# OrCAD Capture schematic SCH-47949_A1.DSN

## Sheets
1 01 TITLE PAGE: title: OM27160B1HN; rev: A1; company: NXP Semiconductors; note: SCH-47949 PDF: SPF-47949; note: 6501 William Cannon Drive West; note: Austin, TX 78735-8598
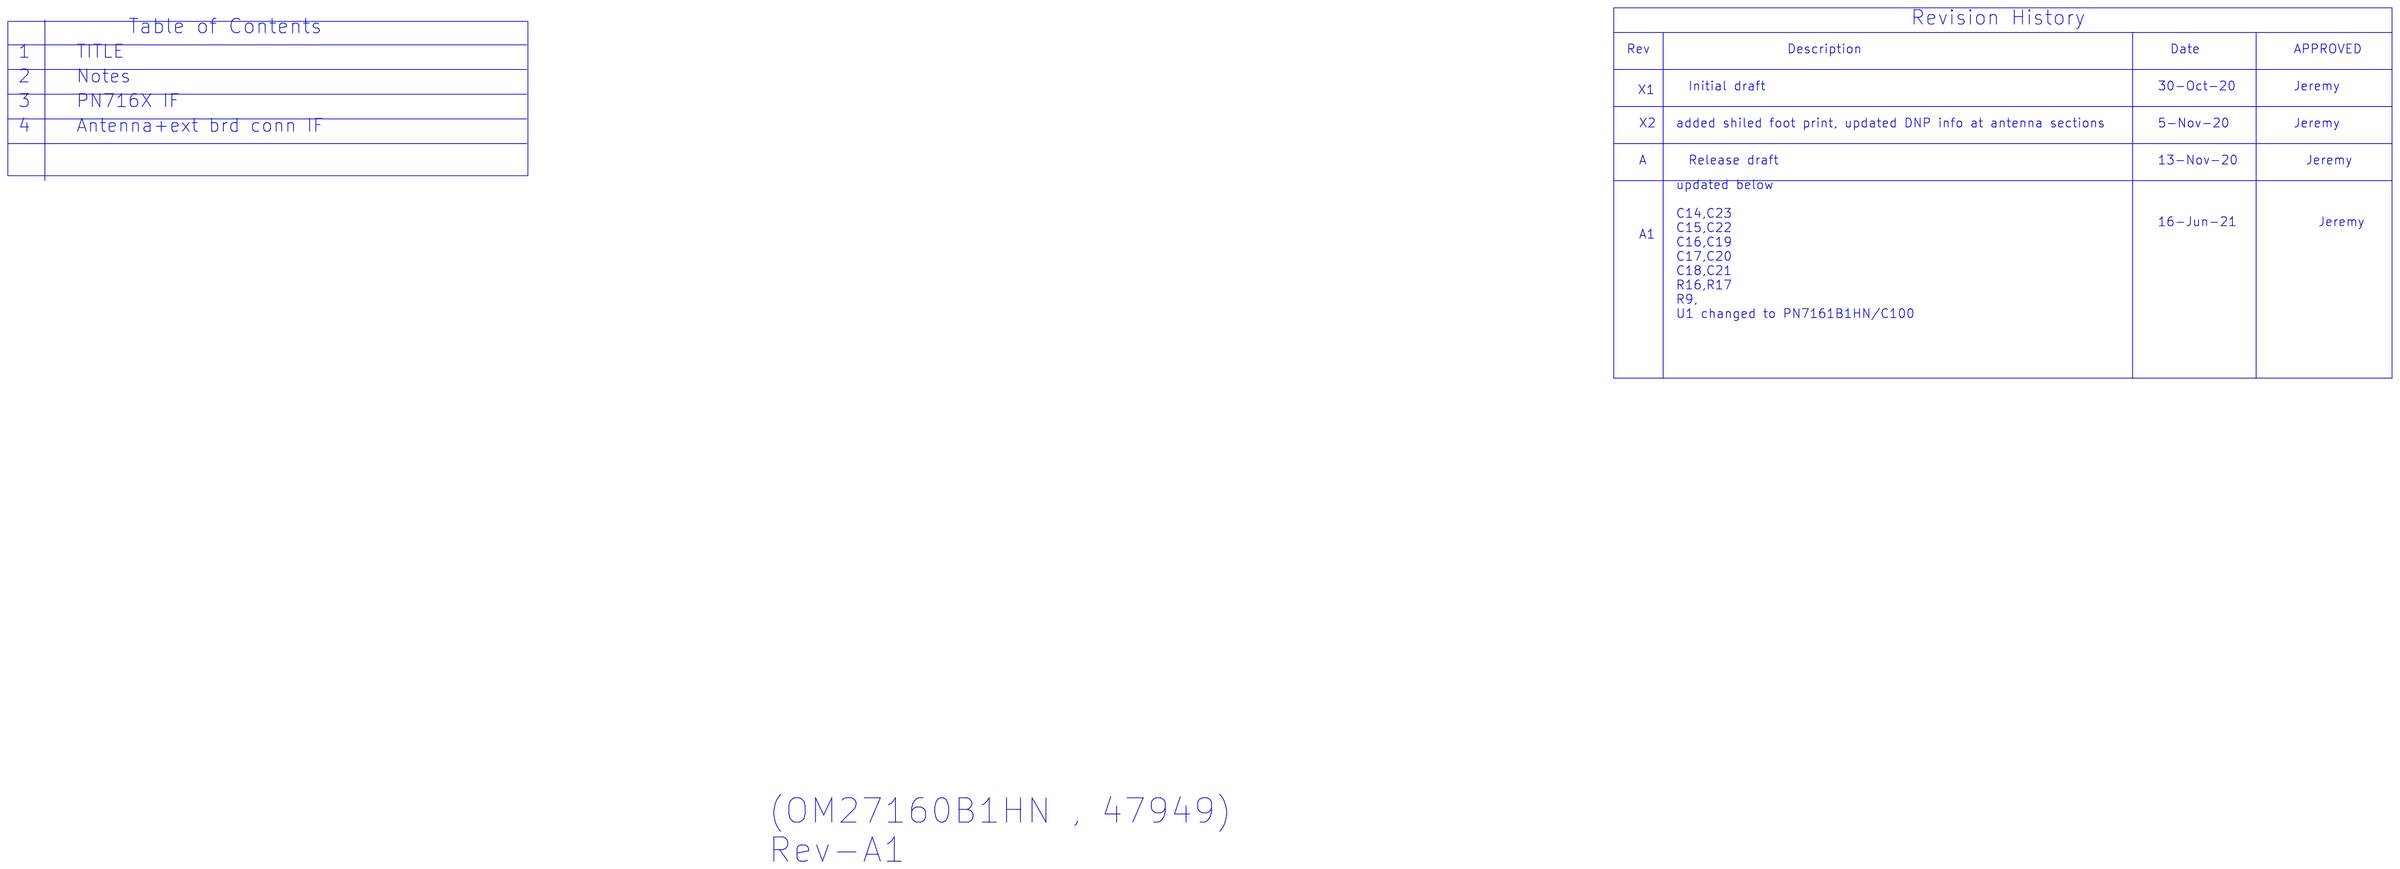
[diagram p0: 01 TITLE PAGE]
2 02 Notes
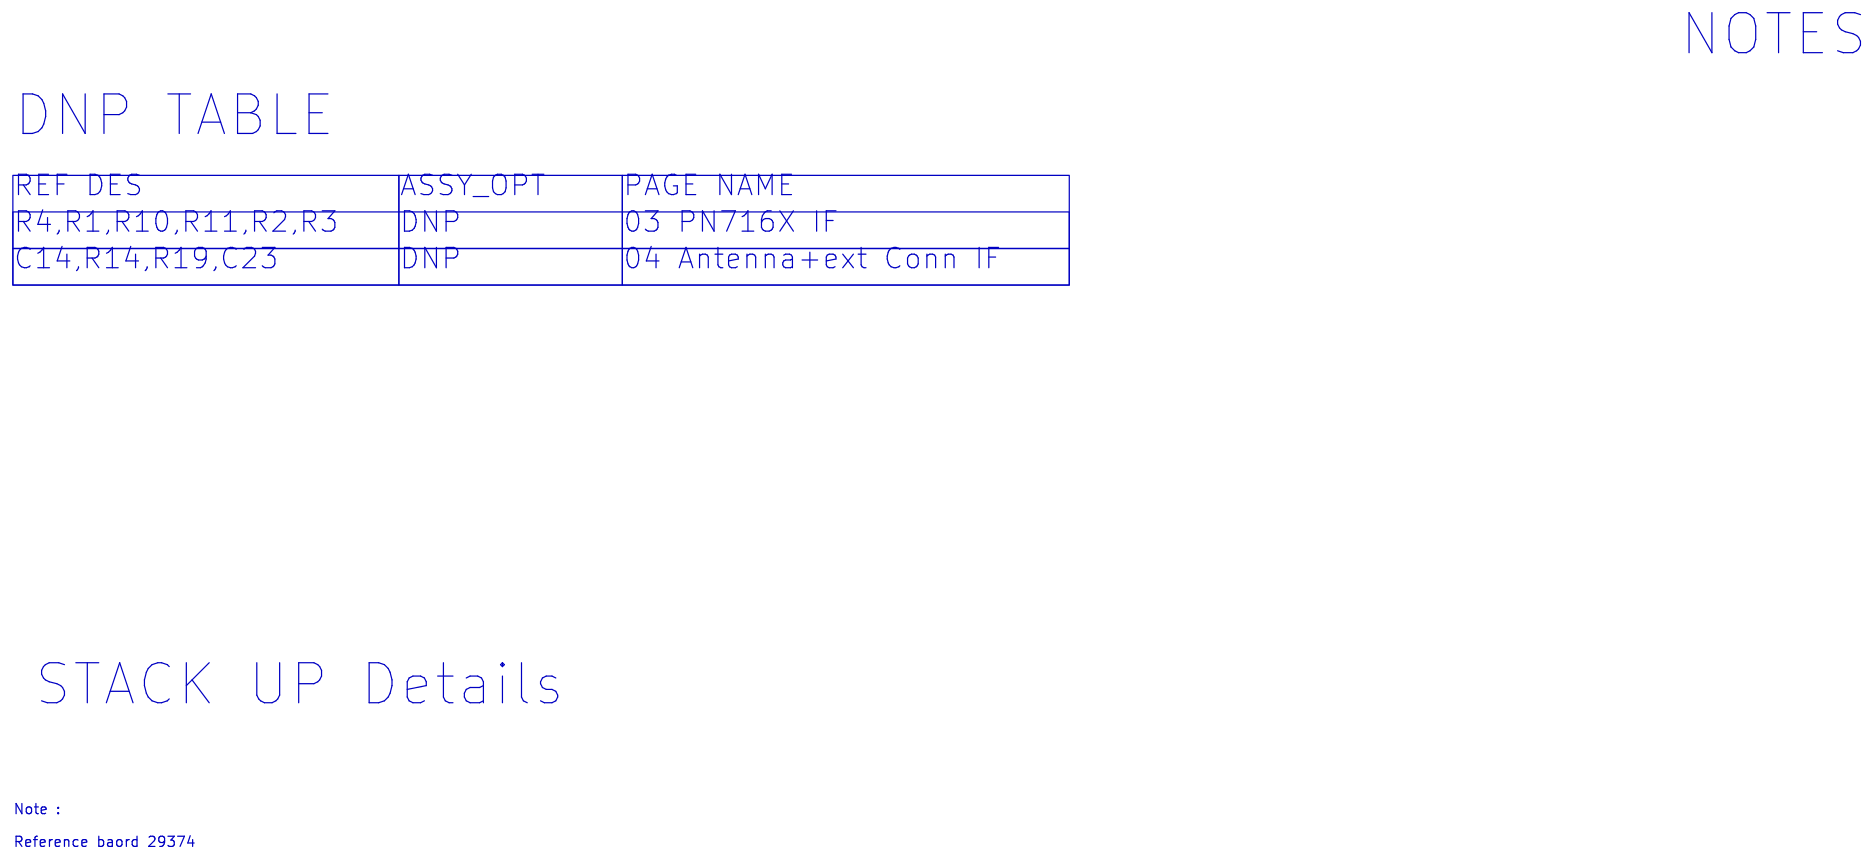
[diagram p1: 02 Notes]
3 03 PN716X IF: size B
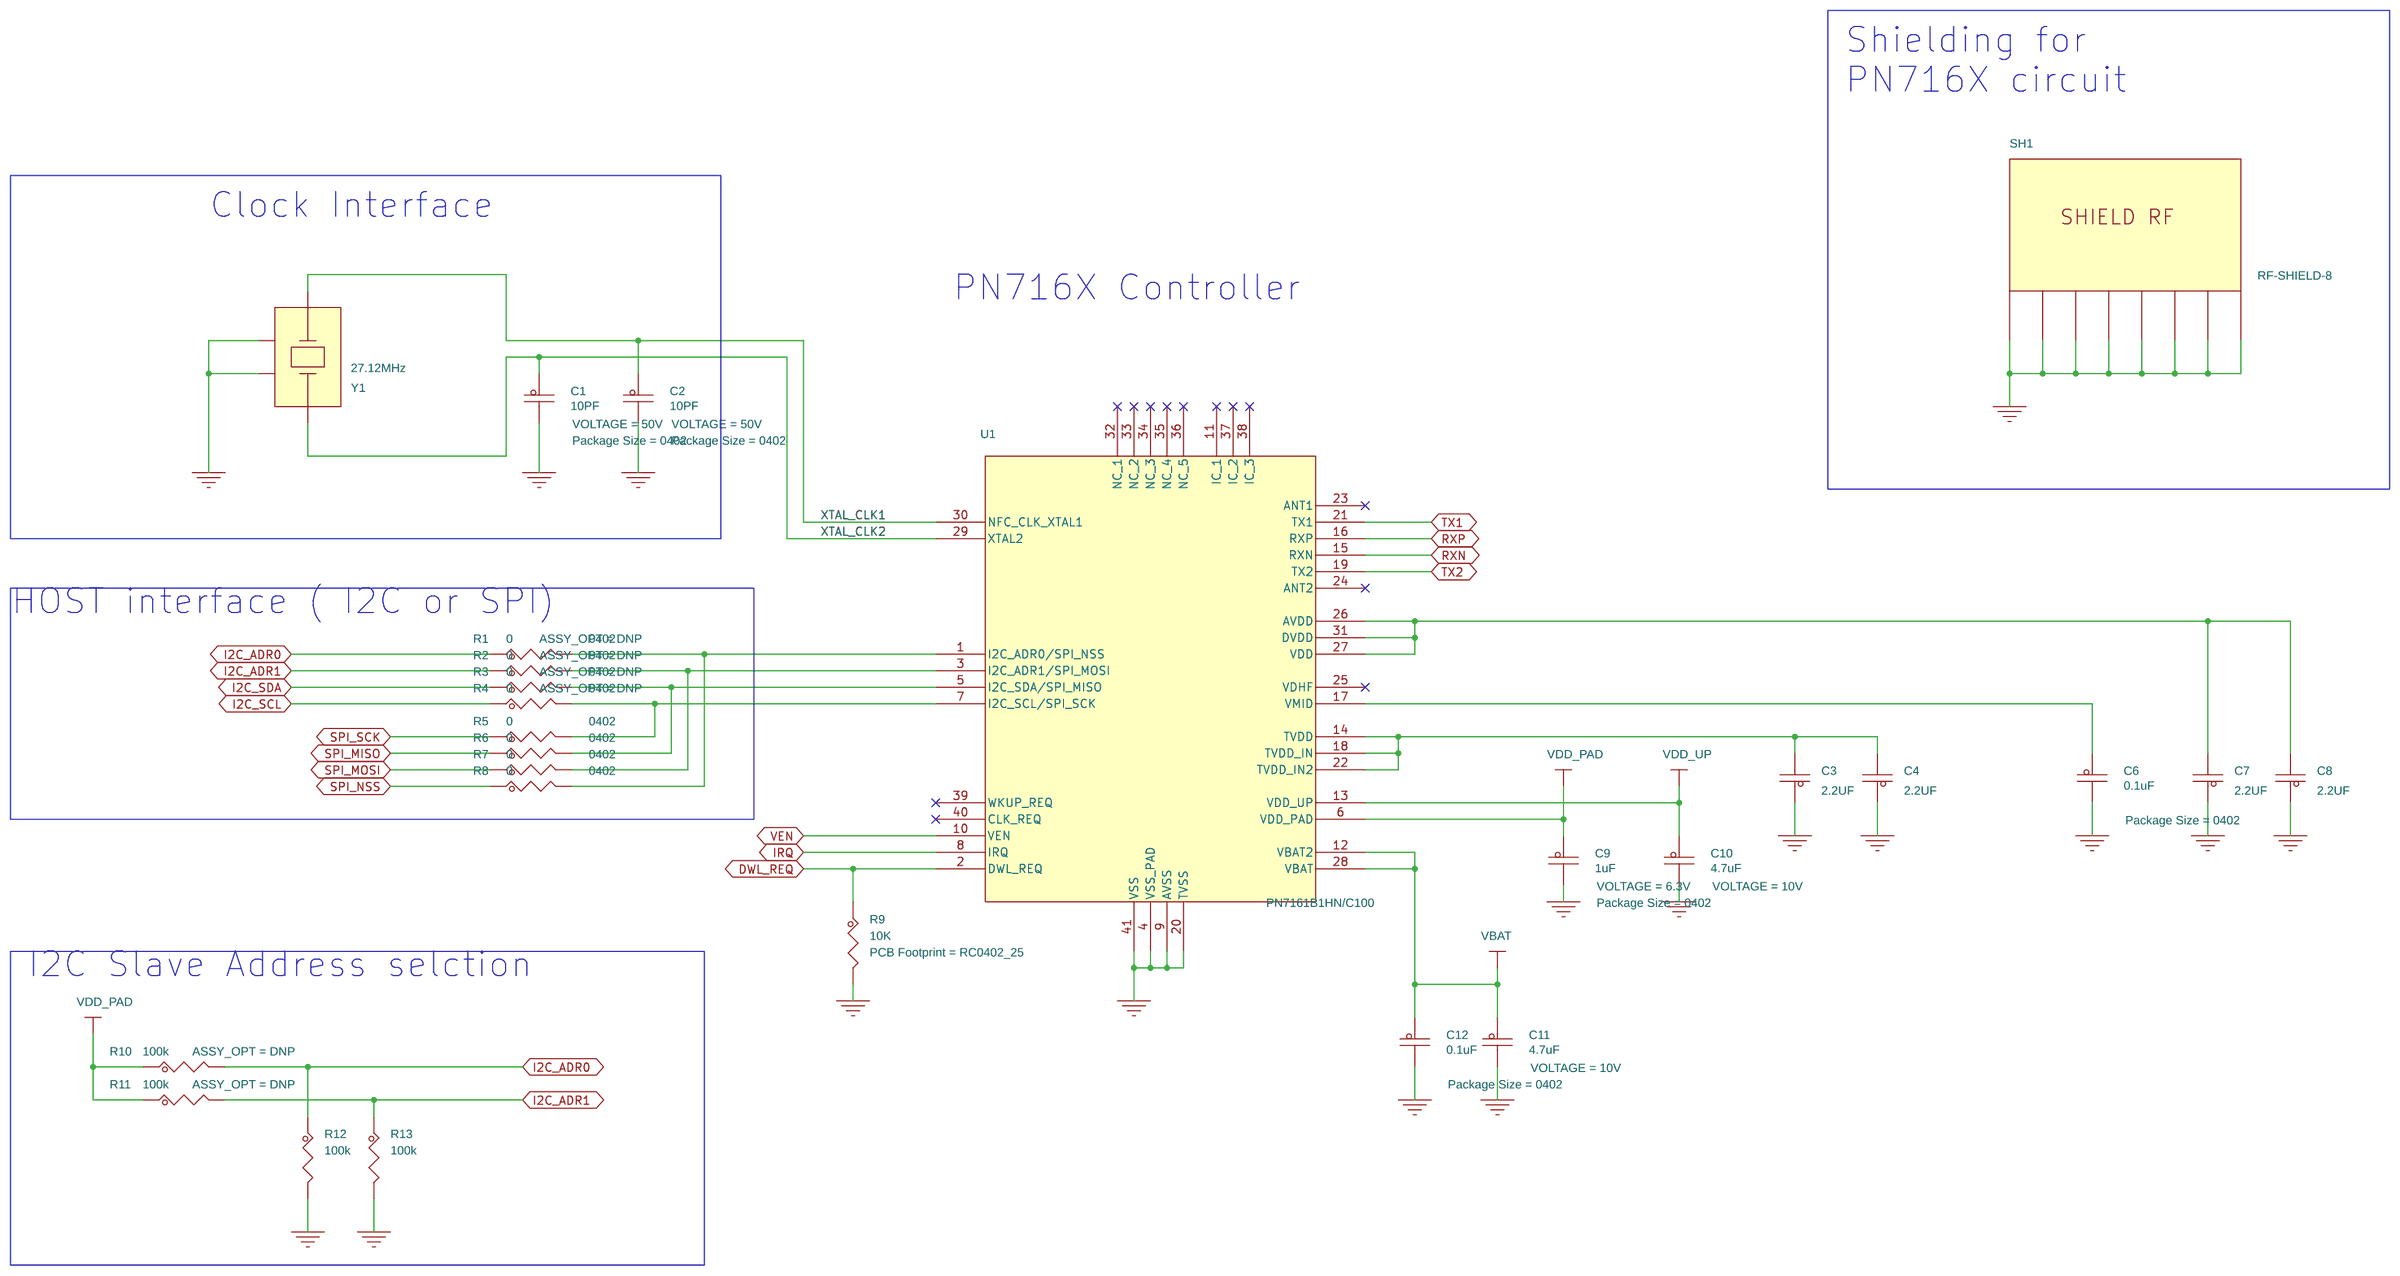
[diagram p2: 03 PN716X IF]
4 04 Antenna+ext Conn IF: size B
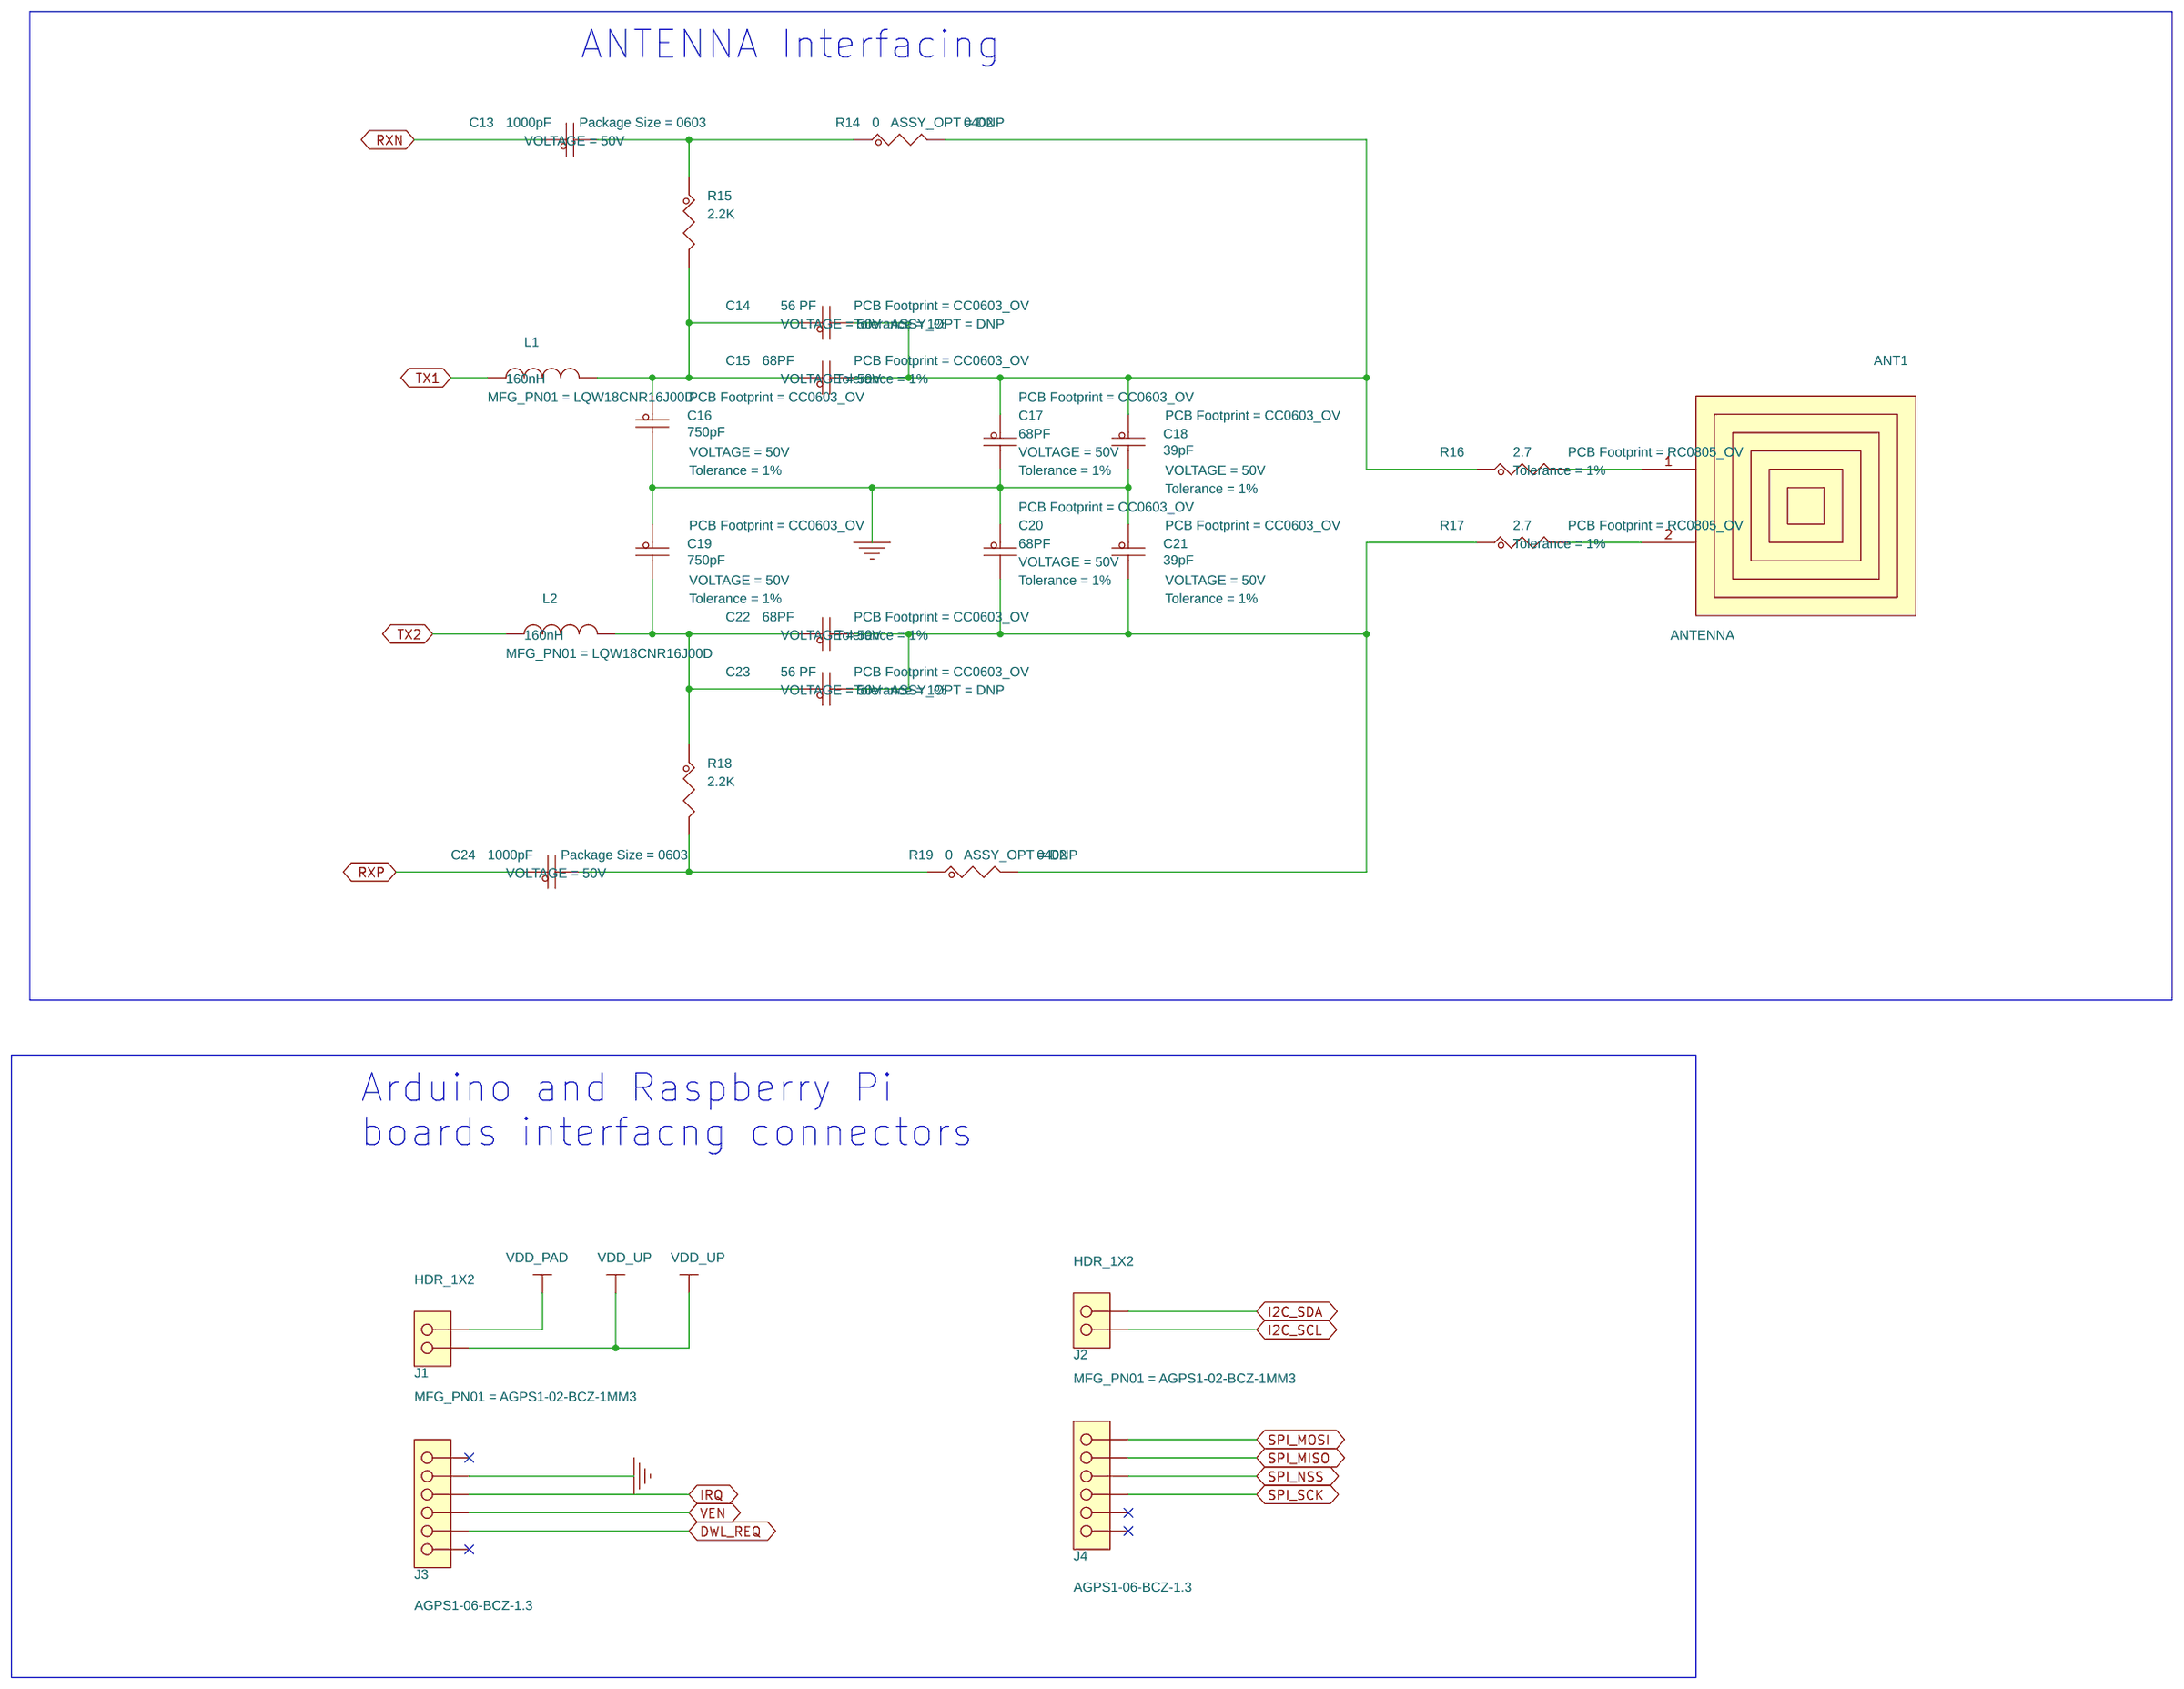
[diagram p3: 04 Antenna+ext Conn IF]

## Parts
sheet 03 PN716X IF
C1  10PF  [CC0402_25]
C2  10PF  [CC0402_25]
C3  2.2UF  [CC0402_25]
C4  2.2UF  [CC0402_25]
C6  0.1uF  [CC0402_25]
C7  2.2UF  [CC0402_25]
C8  2.2UF  [CC0402_25]
C9  1uF  [CC0402_25]
C10  4.7uF  [cc0402_tol0p15]
C11  4.7uF  [cc0402_tol0p15]
C12  0.1uF  [CC0402_25]
R1  0  [RC0402_25]
R2  0  [RC0402_25]
R3  0  [RC0402_25]
R4  0  [RC0402_25]
R5  0  [RC0402_25]
R6  0  [RC0402_25]
R7  0  [RC0402_25]
R8  0  [RC0402_25]
R9  10K  [RC0402_25]
R10  100k  [RC0402_25]
R11  100k  [RC0402_25]
R12  100k  [RC0402_25]
R13  100k  [RC0402_25]
SH1  RF-SHIELD-8  [shield_pn7150_22x22]
U1  PN7161B1HN/C100  [qfn40_0p5_4p25x4p25]
Y1  27.12MHz  [xtal4_2p1x1p7mm_sm]
sheet 04 Antenna+ext Conn IF
ANT1  ANTENNA  [antenna_4t_40X40]
C13  1000pF  [CC0603_OV]
C14  56 PF  [CC0603_OV]
C15  68PF  [CC0603_OV]
C16  750pF  [CC0603_OV]
C17  68PF  [CC0603_OV]
C18  39pF  [CC0603_OV]
C19  750pF  [CC0603_OV]
C20  68PF  [CC0603_OV]
C21  39pF  [CC0603_OV]
C22  68PF  [CC0603_OV]
C23  56 PF  [CC0603_OV]
C24  1000pF  [CC0603_OV]
J1  HDR_1X2  [skt1x2_2p54_th_bse]
J2  HDR_1X2  [skt1x2_2p54_th_bse]
J3  AGPS1-06-BCZ-1.3  [skt1x6_2p54_th_bse]
J4  AGPS1-06-BCZ-1.3  [skt1x6_2p54_th_bse]
L1  160nH  [IND_0603A]
L2  160nH  [IND_0603A]
R14  0  [RC0402_25]
R15  2.2K  [RC0603_OV]
R16  2.7  [RC0805_OV]
R17  2.7  [RC0805_OV]
R18  2.2K  [RC0603_OV]
R19  0  [RC0402_25]

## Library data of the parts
C1 C2 = CAP_NP: CAP CER 10PF 50V 5% C0G 0402; AGILE_PN: 150-75265; CAD_APPROVED: YES; FPLIST: CC0402_25,CC0402_HD,0402_CC,capc0402_l; HEIGHT: 0.635MM; MFG_NAME01: AVX; MFG_PN01: 04025A100JAT2A; Package Size: 0402; Package Type: 7; ROHS: Yes; Tolerance: 5%; VOLTAGE: 50V
C3 C4 C7 C8 = CAP_NP: CAP CER 2.2UF 6.3V 10% X6S 0402; AGILE_PN: 150-80139; CAD_APPROVED: Yes; FPLIST: CC0402_25,CC0402_HD,0402_CC,capc0402_l; HEIGHT: 0.55MM; MFG_NAME01: MURATA; MFG_PN01: GRM155C80J225KE95D; ROHS: Yes; Temp Range: -55 to 105&#8451;
C6 C12 = CAP_NP: CAP CER 0.1uF 16V 10% X7R AEC-Q200 0402; AGILE_PN: 150-79025; CAD_APPROVED: Yes; FPLIST: CC0402_25,CC0402_HD,0402_CC,capc0402_l; HEIGHT: 0.55MM; MFG_NAME01: MURATA; MFG_PN01: GCM155R71C104KA55D; Package Size: 0402; Package Type: ø180mm Reel PAPER; ROHS: Yes
C9 = CAP_NP: CAP CER 1.0uF 6.3V 10% X7R 0402; AGILE_PN: 150-79668; CAD_APPROVED: Yes; FPLIST: CC0402_25,CC0402_HD,0402_CC,capc0402_l; HEIGHT: 0.55MM; MFG_NAME01: MURATA; MFG_PN01: GRM155R70J105KA12D; Package Size: 0402; ROHS: Yes; Tolerance: 10%; VOLTAGE: 6.3V
C10 C11 = CAP_NP: CAP CER 4.7uF 10V 10% X5R 0402; AGILE_PN: 150-80044; CAD_APPROVED: Yes; FPLIST: cc0402_tol0p15,cc0402_tol0p15_ov,0402_cc_nsp; HEIGHT: 0.65MM; MFG_NAME01: SAMSUNG ELECTRO MECHANICS; MFG_PN01: CL05A475KP5NRNC; ROHS: Yes; Tolerance: 10%; VOLTAGE: 10V
R1-R4 R14 R19 = RES: RES MF ZERO OHM 1/16W -- AEC-Q200 0402; AGILE_PN: 470-81849; ASSY_OPT: DNP; CAD_APPROVED: Yes; FPLIST: RC0402_25,RC0402_HD,0402_CC; HEIGHT: 0.45 MM; MFG_NAME01: STACKPOLE ELECTRONICS; MFG_PN01: RMCF0402ZT0R00; Pkg: 0402; ROHS: Yes; Special: DNS
R5-R8 = RES: RES MF ZERO OHM 1/16W -- AEC-Q200 0402; AGILE_PN: 470-81849; CAD_APPROVED: Yes; FPLIST: RC0402_25,RC0402_HD,0402_CC; HEIGHT: 0.45 MM; MFG_NAME01: STACKPOLE ELECTRONICS; MFG_PN01: RMCF0402ZT0R00; Pkg: 0402; ROHS: Yes; Special: DNS
R9 = RES: RES MF 10K 1/16W 1% 0402; AGILE_PN: 470-80452; CAD_APPROVED: Yes; FPLIST: RC0402_25,RC0402_HD,0402_CC,RC0402_X2; HEIGHT: 0.40 MM; MFG_NAME01: VISHAY; MFG_PN01: CRCW040210K0FKEDC; ROHS: Yes; Tolerance: 1%
R10 R11 = RES: RES MF 100k Ohm 1/16W 1% AEC-Q200 0402; AGILE_PN: 470-80502; ASSY_OPT: DNP; CAD_APPROVED: Yes; FPLIST: RC0402_25,RC0402_HD,0402_CC; HEIGHT: 0.4 MM; MFG_NAME01: KOA SPEER; MFG_PN01: RK73H1ETTP1003F; ROHS: Yes; Tolerance: 1%
R12 R13 = RES: RES MF 100k Ohm 1/16W 1% AEC-Q200 0402; AGILE_PN: 470-80502; CAD_APPROVED: Yes; FPLIST: RC0402_25,RC0402_HD,0402_CC; HEIGHT: 0.4 MM; MFG_NAME01: KOA SPEER; MFG_PN01: RK73H1ETTP1003F; ROHS: Yes; Tolerance: 1%
SH1 = SHIELD-RF_8P: SHIELD 850X850MIL RF CUSTOM NO PART TO ORDER; AGILE_PN: 801-76366; CAD_APPROVED: Yes; HEIGHT: 6.7MM; MFG_NAME01: NO PART TO ORDER; Package Type: Shield, Through Hole; ROHS: Yes
U1 = PN7160_HVQFN40_A: IC PN7161B1HN/C100 HVQFN40; AGILE_PN: TMP-CIP-8243; CAD_APPROVED: Yes; HEIGHT: 1.0MM; MFG_NAME01: NXP SEMICONDUCTORS; PRE_APN: 312-83235; ROHS: Yes
Y1 = XTAL_13: XTAL 27.12MHz 15ppm 10pF AEC-Q200 SMT; 3D_Mechanical_Footprint_File: ftp://fcl.am.freescale.net/ALLEGRO/step/xtal4_2p1x1p7mm_sm.STEP; AGILE_PN: 230-78461; CAD_APPROVED: Yes; Frequency Tolerance: 15ppm; HEIGHT: 0.5MM; MFG_NAME01: NDK; MFG_PN01: NX2016SA-27.12MHZ-EXS00A-CS01188; Package Size: 0.079" L x 0.063" W (2.00mm x 1.60mm); ROHS: Yes; Temp Range: -40°C to +125°C
ANT1 = L104: PCB ANTENNA 40X40MM NO PART ORDER; AGILE_PN: 510-78383; CAD_APPROVED: YES; HEIGHT: 0.127 MM; ROHS: YES
C13 C24 = CAP_NP: CAP CER 1000pF 50V 1% C0G 0603; AGILE_PN: 150-79073; CAD_APPROVED: Yes; FPLIST: CC0603_OV,CC0603,0603_CC; HEIGHT: 0.9MM; MFG_NAME01: TDK; MFG_PN01: C1608C0G1H102F080AA; Package Size: 0603; ROHS: Yes; Tolerance: 1%; VOLTAGE: 50V
C14 C23 = CAP_NP: CAP CER 56PF 50V 1% C0G 0603; AGILE_PN: 150-78639; ASSY_OPT: DNP; CAD_APPROVED: Yes; FPLIST: CC0603_OV,CC0603,0603_CC; HEIGHT: 0.9 MM; MFG_NAME01: AVX; MFG_PN01: 06035A560FAT2A; ROHS: Yes; Tolerance: 1%; VOLTAGE: 50V
C15 C17 C20 C22 = CAP_NP: CAP CER 68PF 50V 1% C0G 0603; AGILE_PN: 150-76710; CAD_APPROVED: Yes; FPLIST: CC0603_OV,CC0603,0603_CC; HEIGHT: 0.86MM; MFG_NAME01: AVX; MFG_PN01: 06035A680FAT2A; Package Size: 0603; Package Type: 7; ROHS: Yes; Tolerance: 1%; VOLTAGE: 50V
C16 C19 = CAP_NP: CAP CER 750pF 50V 1% C0G 0603; 3D_Mechanical_Footprint_File: ftp://fcl.am.freescale.net/ALLEGRO/step/cc0603_ov.STEP; AGILE_PN: 150-81380; CAD_APPROVED: Yes; FPLIST: CC0603_OV,CC0603,0603_CC; HEIGHT: 0.87MM; MFG_NAME01: KEMET; MFG_PN01: C0603C751F5GAC7867; Package Size: 0603 (1608 Metric); Package Type: Surface Mount, MLCC; ROHS: Yes; Rated Voltage: 50V; Temp Range: -55 °C to +125 °C; Tolerance: 1%; VOLTAGE: 50V
C18 C21 = CAP_NP: CAP CER 39pF 50V 1% C0G AEC-Q200 0603; 3D_Mechanical_Footprint_File: ftp://fcl.am.freescale.net/ALLEGRO/step/cc0603_ov.STEP; AGILE_PN: 150-81379; CAD_APPROVED: Yes; FPLIST: CC0603_OV,CC0603,0603_CC; HEIGHT: 0.9MM; MFG_NAME01: SAMSUNG; MFG_PN01: CL10C390FB81PNC; Package Size: 0603 (1608 Metric); Package Type: Surface Mount; ROHS: Yes; Rated Voltage: 50V; Temp Range: -55C to +125C; Tolerance: 1%; VOLTAGE: 50V
J1 J2 = CONN_HDR_2X1: CON 1X2 SKT TH 100MIL 31H SN 134L; AGILE_PN: 210-82544; CAD_APPROVED: Yes; HEIGHT: 0.8 MM; MFG_NAME01: ANTELEC; MFG_PN01: AGPS1-02-BCZ-1MM3; Package Size: 5.08 x2.5mm; ROHS: Yes; Temp Range: -55C - 125C
J3 J4 = CONN_HDR_6X1: CON 1X6 SKT TH 100MIL 31H SN 134L; AGILE_PN: 210-81718; CAD_APPROVED: Yes; HEIGHT: 0.8MM; MFG_NAME01: ANTELEC; ROHS: Yes; Temp Range: -55 to 125 C
L1 L2 = INDUCTOR: IND WW 160nH@10MHZ 1A 5% 0603; 3D_Mechanical_Footprint_File: ind_0603a; AGILE_PN: 180-78648; CAD_APPROVED: Yes; FPLIST: IND_0603A,cc0603_0805_nsp; HEIGHT: 0.95MM; MFG_NAME01: MURATA; MFG_PN01: LQW18CNR16J00D; Package Size: 0603; ROHS: Yes; Temp Range: -40C to +85C
R15 R18 = RES: RES MF 2.2K 1/10W 5% AEC-Q200 0603; AGILE_PN: 470-80807; CAD_APPROVED: Yes; FPLIST: RC0603_OV,RC0603,0603_CC; HEIGHT: 0.55MM; MFG_NAME01: PANASONIC; MFG_PN01: ERJ3GEYJ222V; ROHS: Yes; Tolerance: 5%
R16 R17 = RES: RES MF 2.7 OHM 1/8W 1% AEC-Q200 0805; AGILE_PN: 470-82212; CAD_APPROVED: Yes; FPLIST: RC0805_OV,RC0805,0805_CC; HEIGHT: 0.5MM; MFG_NAME01: VISHAY INTERTECHNOLOGY; MFG_PN01: CRCW08052R70FKEA; ROHS: Yes; Temp Range: -55C to +155C; Tolerance: 1%

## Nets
GND: C1.2 C2.2 C3.1 C4.1 C6.2 C7.1 C8.1 C9.2 C10.2 C11.2 C12.2 C16.2 C17.2 C18.2 C19.1 C20.1 C21.1 J3.2 R9.2 R12.2 R13.2 SH1.1 SH1.2 SH1.3 SH1.4 SH1.5 SH1.6 SH1.7 SH1.8 U1.4(VSS_PAD) U1.9(AVSS) U1.20(TVSS) U1.41(VSS) Y1.2 Y1.4
VBAT: C10.1 C11.1 C12.1 J1.2 U1.12(VBAT2) U1.13(VDD_UP) U1.28(VBAT)
VDD_PAD: C9.1 J1.1 R10.1 R11.1 U1.6(VDD_PAD)
DWL_REQ: J3.5 R9.1 U1.2(DWL_REQ)
I2C_ADR0: R1.1 R10.2 R12.1
I2C_ADR1: R2.1 R11.2 R13.1
I2C_SCL: J2.2 R4.1
I2C_SDA: J2.1 R3.1
IRQ: J3.3 U1.8(IRQ)
RXN: C13.1 U1.15(RXN)
RXP: C24.1 U1.16(RXP)
SPI_MISO: J4.2 R6.1
SPI_MOSI: J4.1 R7.1
SPI_NSS: J4.3 R8.1
SPI_SCK: J4.4 R5.1
TX1: L1.1 U1.21(TX1)
TX2: L2.1 U1.19(TX2)
VEN: J3.4 U1.10(VEN)
XTAL_CLK1: C2.1 U1.30(NFC_CLK_XTAL1) Y1.3
XTAL_CLK2: C1.1 U1.29(XTAL2) Y1.1
N17603649: R1.2 R8.2 U1.1(I2C_ADR0/SPI_NSS)
N17603709: R2.2 R7.2 U1.3(I2C_ADR1/SPI_MOSI)
N17603712: R3.2 R6.2 U1.5(I2C_SDA/SPI_MISO)
N17603715: R4.2 R5.2 U1.7(I2C_SCL/SPI_SCK)
N17605280: C3.2 C4.2 U1.14(TVDD) U1.18(TVDD_IN) U1.22(TVDD_IN2)
N17605634: C6.1 U1.17(VMID)
N17606479: C7.2 C8.2 U1.26(AVDD) U1.27(VDD) U1.31(DVDD)
N17608331: ANT1.1 R16.2
N17608352: ANT1.2 R17.2
N17608403: C14.2 C15.2 C17.1 C18.1 R14.2 R16.1
N17608431: C20.2 C21.2 C22.2 C23.2 R17.1 R19.2
N17608486: C14.1 C15.1 C16.1 L1.2 R15.2
N17608550: C19.2 C22.1 C23.1 L2.2 R18.1
N17608728: C24.2 R18.2 R19.1
N17608753: C13.2 R14.1 R15.1

Not connected (* = marked no-connect by the designer): J3 1* 6*; J4 5* 6*; U1 11(IC_1)* 23(ANT1)* 24(ANT2)* 25(VDHF)* 32(NC_1)* 33(NC_2)* 34(NC_3)* 35(NC_4)* 36(NC_5)* 37(IC_2)* 38(IC_3)* 39(WKUP_REQ)* 40(CLK_REQ)*

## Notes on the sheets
sheet 1
- Revision History
- Table of Contents
- 1
- TITLE
- Rev
- Description
- Date
- APPROVED
- 2
- Notes
- X1
- Initial draft
- 30-Oct-20
- Jeremy
- 3
- PN716X IF
- 4
- Antenna+ext brd conn IF
- X2
- added shiled foot print, updated DNP info at antenna sections
- 5-Nov-20
- Jeremy
- A
- Release draft
- 13-Nov-20
- Jeremy
- updated below
  C14,C23
  C15,C22
  C16,C19
  C17,C20
  C18,C21
  R16,R17
  R9,
  U1 changed to PN7161B1HN/C100
- 16-Jun-21
- Jeremy
- A1
- (OM27160B1HN , 47949)
  Rev-A1
sheet 2
- NOTES
- DNP TABLE
- REF DES
- ASSY_OPT
- PAGE NAME
- R4,R1,R10,R11,R2,R3
- DNP
- 03 PN716X IF
- C14,R14,R19,C23
- DNP
- 04 Antenna+ext Conn IF
- STACK UP Details
- Note :
  Reference baord 29374
sheet 3
- Shielding for
  PN716X circuit
- Clock Interface
- PN716X Controller
- HOST interface ( I2C or SPI)
- I2C Slave Address selction
sheet 4
- ANTENNA Interfacing
- Arduino and Raspberry Pi
  boards interfacng connectors
